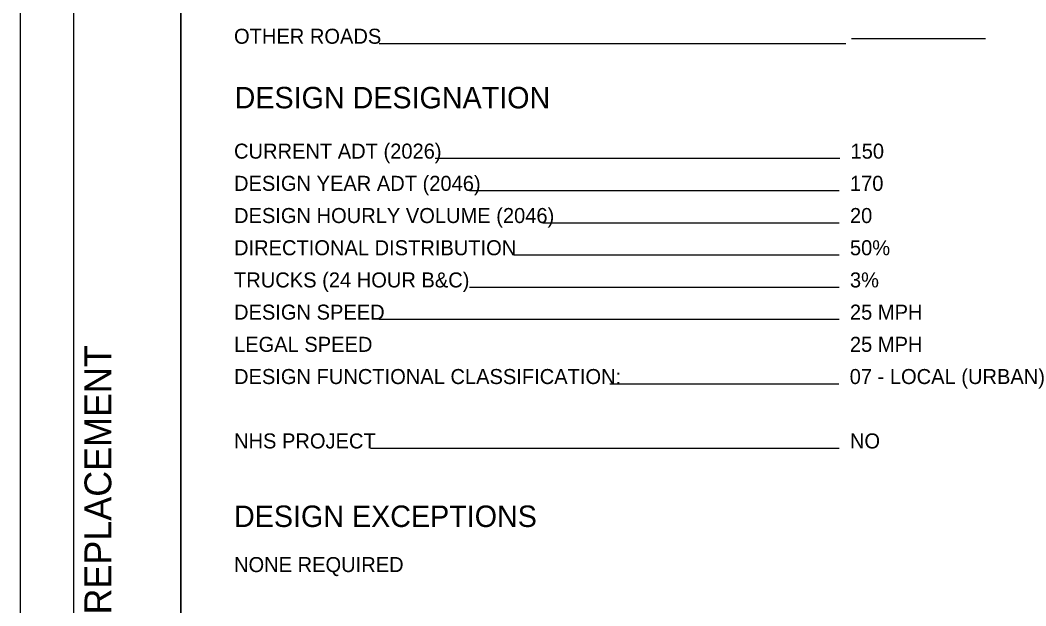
# Model space of a CAD drawing. Extents: x -7.1 to 34, y 0 to 22.
# Drawn here: x 0 to 9.38, y 5.64 to 11.1 of the extents above; entities that cross this region are included whole.
import ezdxf

# ---------------------------------------------------------------- set-up
doc = ezdxf.new("R2010")
doc.units = 0
for name, color, linetype in [('SH_Border', 7, 'Continuous'), ('SH_Cut_Line', 7, 'Continuous'), ('SH_Data', 7, 'Continuous'), ('SH_Text', 7, 'Continuous')]:
    doc.layers.add(name, color=color, linetype=linetype)

msp = doc.modelspace()

# ---------------------------------------------------------------- linework, layer by layer
at = {"layer": 'SH_Border'}
for points in [[(0.5, 21.5), (1.5, 21.5), (1.5, 0.5), (0.5, 0.5)], [(1.5, 21.5), (33.5, 21.5), (33.5, 0.5), (1.5, 0.5)]]:
    msp.add_lwpolyline(points, close=True, dxfattribs=at)
at = {"layer": 'SH_Cut_Line'}
msp.add_lwpolyline([(0, 0), (34, 0), (34, 22), (0, 22)], close=True, dxfattribs=at)
at = {"layer": 'SH_Data'}
for p, q in [((9, 10.9223), (7.75, 10.9223)), ((7.7, 10.8767), (3.3471, 10.8767)), ((7.6424, 9.8062), (3.871, 9.8062)), ((7.6368, 9.5062), (4.1885, 9.5062)), ((7.6368, 9.2062), (4.8723, 9.2062)), ((7.6368, 8.9062), (4.6037, 8.9062)), ((7.6368, 8.6062), (4.1885, 8.6062)), ((7.6368, 8.3062), (3.346, 8.3062)), ((7.6346, 7.7062), (5.4969, 7.7062)), ((7.6368, 7.1062), (3.2669, 7.1062))]:
    msp.add_line(p, q, dxfattribs=at)

# ---------------------------------------------------------------- texts
msp.add_text('DESIGN DESIGNATION', height=0.2, dxfattribs=at).set_placement((2, 10.2747))
msp.add_text('HAS-BRIDGE STREET BRIDGE REPLACEMENT', height=0.25, rotation=90, dxfattribs=at).set_placement((0.85, 0.6))
at = {"layer": 'SH_Text'}
for s, height, p in [('OTHER ROADS', 0.14, (1.9944, 10.8767)), ('CURRENT ADT (2026)', 0.14, (1.9944, 9.8062)), ('150', 0.14, (7.7424, 9.8062)), ('DESIGN YEAR ADT (2046)', 0.14, (1.9944, 9.5062)), ('170', 0.14, (7.7368, 9.5062)), ('DESIGN HOURLY VOLUME (2046)', 0.14, (1.9944, 9.2062)), ('20', 0.14, (7.7368, 9.2062)), ('DIRECTIONAL DISTRIBUTION', 0.14, (1.9944, 8.9062)), ('50%', 0.14, (7.7368, 8.9062)), ('TRUCKS (24 HOUR B&C)', 0.14, (1.9944, 8.6062)), ('3%', 0.14, (7.7368, 8.6062)), ('DESIGN SPEED', 0.14, (1.9944, 8.3062)), ('25 MPH', 0.14, (7.7368, 8.3062)), ('LEGAL SPEED', 0.14, (1.9944, 8.0062)), ('25 MPH', 0.14, (7.7368, 8.0062)), ('DESIGN FUNCTIONAL CLASSIFICATION:', 0.14, (1.9944, 7.7062)), ('07 - LOCAL (URBAN)', 0.14, (7.7346, 7.7062)), ('NHS PROJECT', 0.14, (1.9944, 7.1062)), ('NO', 0.14, (7.7368, 7.1062)), ('DESIGN EXCEPTIONS', 0.2, (1.9944, 6.3744)), ('NONE REQUIRED', 0.14, (1.9944, 5.9544))]:
    msp.add_text(s, height=height, dxfattribs=at).set_placement(p)

doc.saveas('drawing.dxf')
